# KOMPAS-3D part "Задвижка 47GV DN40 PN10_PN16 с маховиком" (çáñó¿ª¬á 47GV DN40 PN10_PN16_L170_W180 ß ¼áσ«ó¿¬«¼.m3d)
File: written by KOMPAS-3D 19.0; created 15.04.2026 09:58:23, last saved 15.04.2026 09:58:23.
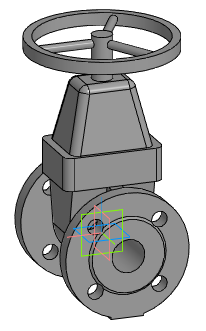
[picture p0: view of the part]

Document properties: Автор: Евгений; Полное имя файла: Z:\3.Личные\kachalov\3d для проектировщиков\2.1 Тип 47GV, 47GV.Z\Задвижка 47GV_DN40-DN600\stp_Задвижка 47GV\Задвижка 47GV DN40 PN10_PN16_L170_W180 с маховиком.m3d

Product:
- Part/product: Задвижка 47GV DN40 PN10_PN16 с маховиком

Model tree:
1. Операция без истории:1  (labels: Задвижка 47GV DN40 PN10_PN16 с маховиком)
